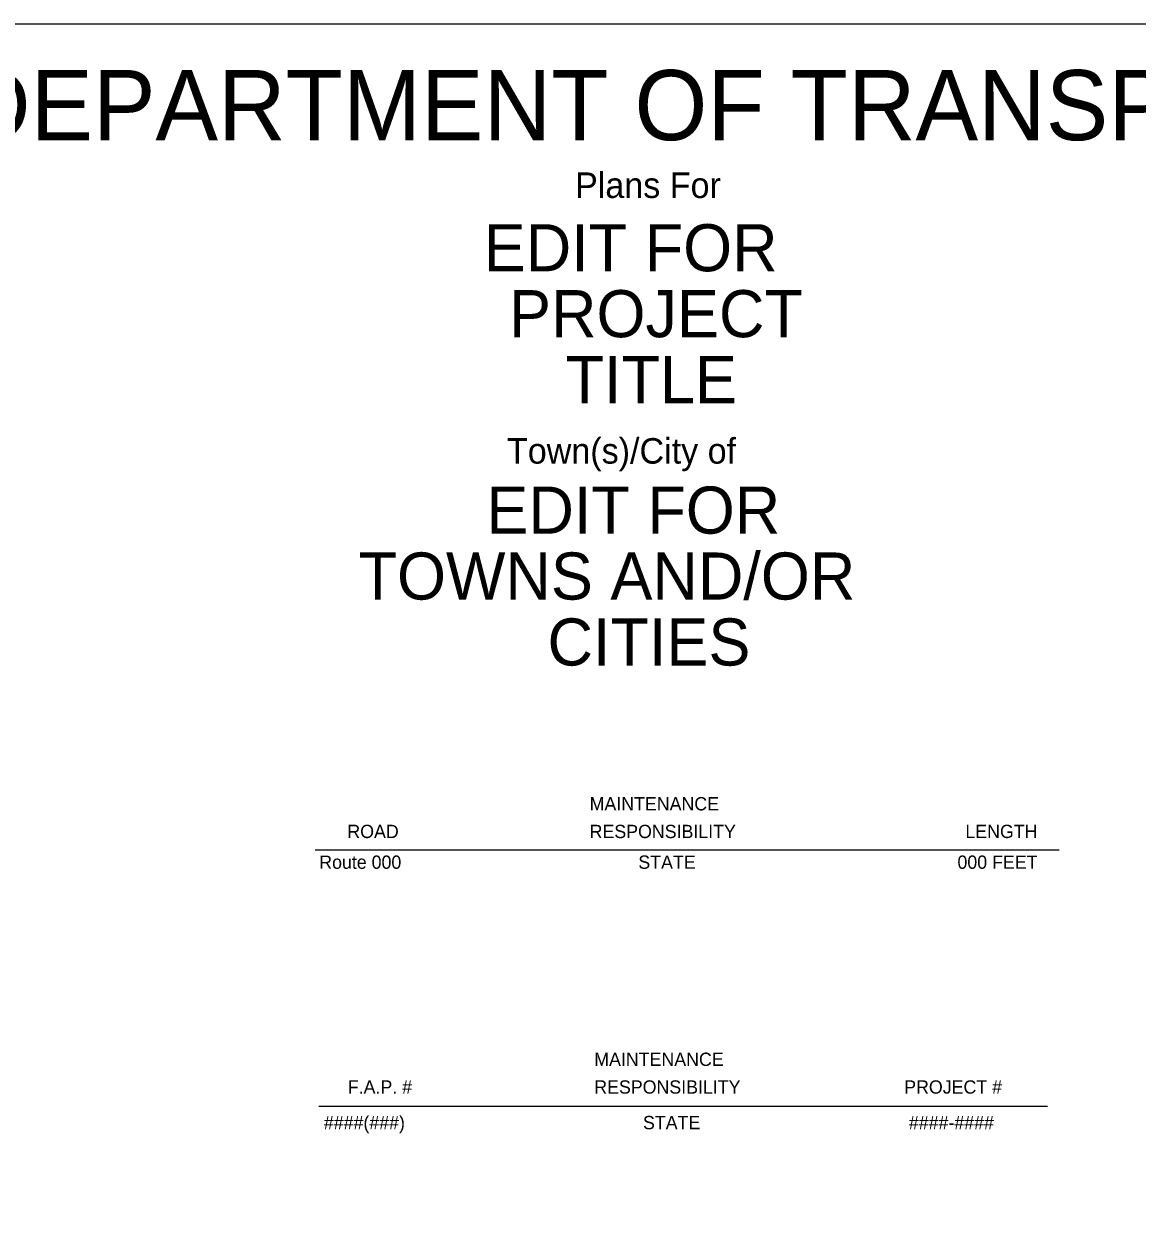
# Model space of a CAD drawing. Extents: x 0 to 2603, y -226 to 830.
# Drawn here: x 401.9 to 803.8, y 398.7 to 830 of the extents above; entities that cross this region are included whole.
import ezdxf

# ---------------------------------------------------------------- set-up
doc = ezdxf.new("R2010")
doc.units = 0
for name, color, linetype in [('CT_Border_Perimeter_Shape', 7, 'Continuous'), ('CT_TSH_Annotation_Edit', 7, 'Continuous'), ('CT_TSH_Annotation_Locked', 7, 'Continuous'), ('CT_TSH_Annotation_Maintainance_Resposibility_1', 7, 'Continuous'), ('CT_TSH_Annotation_Maintainance_Resposibility_2', 7, 'Continuous')]:
    doc.layers.add(name, color=color, linetype=linetype)

msp = doc.modelspace()

# ---------------------------------------------------------------- linework, layer by layer
at = {"layer": 'CT_Border_Perimeter_Shape'}
msp.add_lwpolyline([(0, 830), (1270, 830), (1270, 0), (0, 0)], close=True, dxfattribs=at)
at = {"layer": 'CT_TSH_Annotation_Maintainance_Resposibility_1'}
msp.add_line((506.98, 531.93), (775.68, 531.93), dxfattribs=at)
at = {"layer": 'CT_TSH_Annotation_Maintainance_Resposibility_2'}
msp.add_line((508.31, 439.39), (771.42, 439.39), dxfattribs=at)

# ---------------------------------------------------------------- texts
at = {"layer": 'CT_TSH_Annotation_Edit'}
for s, height, p in [('EDIT FOR ', 17, (567.9, 740.72)), ('PROJECT', 17, (577.02, 716.92)), ('TITLE', 17, (597.42, 693.12)), ('Town(s)/City of', 9.2, (576.28, 671.31)), ('EDIT FOR ', 17, (568.86, 646.04)), ('TOWNS AND/OR', 17, (522.7, 622.24)), ('CITIES', 17, (590.91, 598.44))]:
    msp.add_text(s, height=height, dxfattribs=at).set_placement(p)
at = {"layer": 'CT_TSH_Annotation_Locked'}
for s, height, p in [('CONNECTICUT DEPARTMENT OF TRANSPORTATION', 25.3, (124.23, 788.04)), ('Plans For', 9.2, (600.86, 767.18))]:
    msp.add_text(s, height=height, dxfattribs=at).set_placement(p)
at = {"layer": 'CT_TSH_Annotation_Maintainance_Resposibility_1'}
for s, p in [('MAINTENANCE', (606.12, 546.16)), ('ROAD', (518.66, 536.18)), ('RESPONSIBILITY', (606.12, 536.16)), ('LENGTH', (741.77, 536.18)), ('Route 000', (508.51, 525.08)), ('STATE', (623.71, 525.08)), ('000 FEET', (738.91, 525.08))]:
    msp.add_text(s, height=4.8, dxfattribs=at).set_placement(p)
at = {"layer": 'CT_TSH_Annotation_Maintainance_Resposibility_2'}
for s, p in [('MAINTENANCE', (607.79, 453.94)), ('F.A.P. #', (518.82, 443.94)), ('RESPONSIBILITY', (607.79, 443.94)), ('PROJECT #', (719.69, 443.94)), ('####(###)', (510.18, 431.1)), ('STATE', (625.38, 431.1)), ('####-####', (721.38, 431.1))]:
    msp.add_text(s, height=4.8, dxfattribs=at).set_placement(p)

doc.saveas('drawing.dxf')
